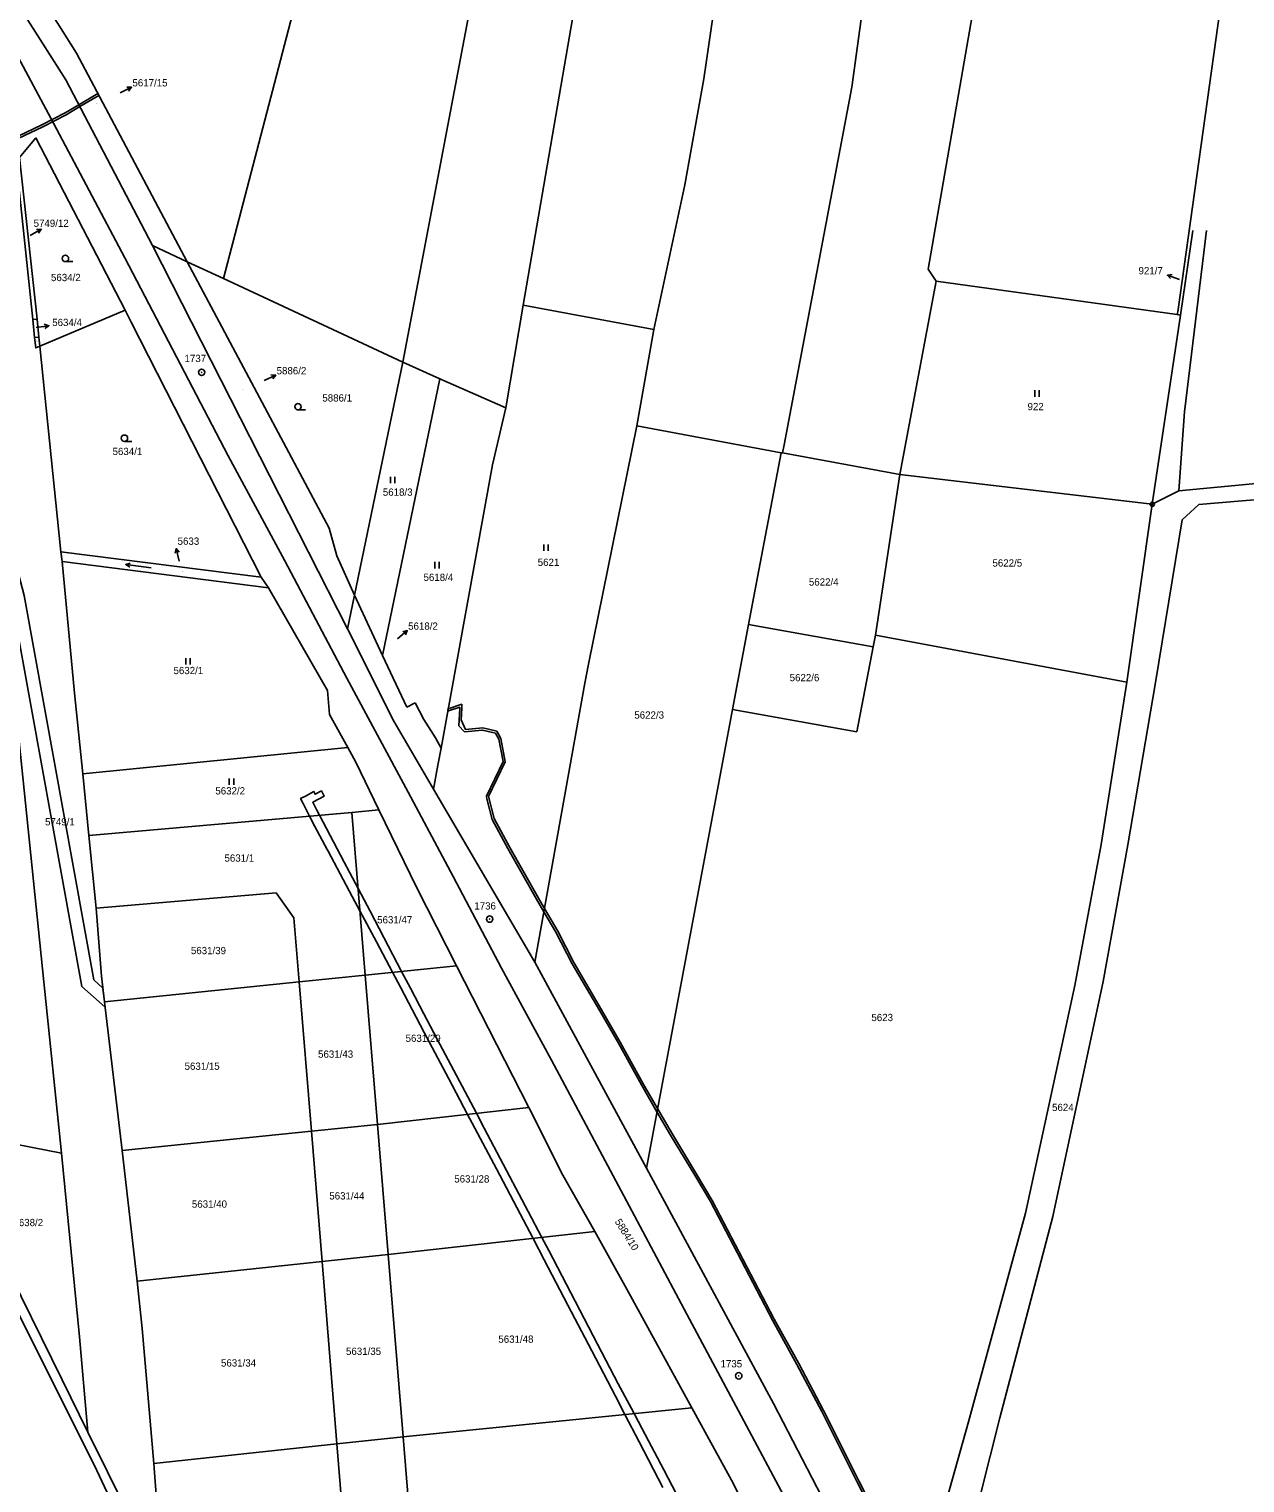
# Model space of a CAD drawing. Extents: x -735092 to -733385, y -1122435 to -1118992.
# Drawn here: x -734093.3 to -733808.8, y -1121933.9 to -1121593.8 of the extents above; entities that cross this region are included whole.
import ezdxf

# ---------------------------------------------------------------- set-up
doc = ezdxf.new("R2010")
doc.units = 0
for name, color, linetype in [('Vrstva 1', 7, 'Continuous'), ('Vrstva 10', 7, 'Continuous'), ('Vrstva 13', 7, 'Continuous'), ('Vrstva 16', 7, 'Continuous'), ('Vrstva 17', 7, 'Continuous'), ('Vrstva 18', 7, 'Continuous'), ('Vrstva 25', 7, 'Continuous'), ('Vrstva 27', 7, 'Continuous'), ('Vrstva 4', 7, 'Continuous')]:
    doc.layers.add(name, color=color, linetype=linetype)

msp = doc.modelspace()

# ---------------------------------------------------------------- linework, layer by layer
at = {"layer": 'Vrstva 1'}
for points in [[(-733875.65, -1121424.26), (-733900.77, -1121607.37)], [(-733977.66, -1121658.4), (-733946.34, -1121476.34)], [(-734005.87, -1121671.76), (-733978.34, -1121526.72)], [(-733811.12, -1121564.42), (-733824.52, -1121659.94)], [(-734101.71, -1121568.57), (-734082.23, -1121599.47)], [(-734100.75, -1121580.51), (-734084.7, -1121605.68)], [(-733882.88, -1121650), (-733870.98, -1121581.23)], [(-734029.87, -1121583.41), (-734047.83, -1121652.19)], [(-734082.23, -1121599.47), (-734056.29, -1121648.23)], [(-734084.7, -1121605.68), (-734064.45, -1121644.4)], [(-733900.77, -1121607.37), (-733916.64, -1121691.05)], [(-734095.52, -1121623.85), (-734091.73, -1121619.24)], [(-734091.73, -1121619.24), (-734070.84, -1121659.55)], [(-734092.41, -1121661.77), (-734096.3, -1121624.74), (-734095.52, -1121623.85)], [(-734095.52, -1121623.85), (-734091.45, -1121661.68)], [(-733823.82, -1121660.72), (-733821, -1121640.92)], [(-733817.78, -1121640.91), (-733822.95, -1121683.35)], [(-734064.45, -1121644.4), (-734018.79, -1121734.08)], [(-734064.45, -1121644.4), (-734056.29, -1121648.23)], [(-734056.29, -1121648.23), (-734023.08, -1121710.55)], [(-734056.29, -1121648.23), (-734047.83, -1121652.19)], [(-734047.83, -1121652.19), (-734005.87, -1121671.76)], [(-733889.57, -1121698.02), (-733881.01, -1121652.76)], [(-733881.01, -1121652.76), (-733882.88, -1121650)], [(-733824.6, -1121660.61), (-733881.01, -1121652.76)], [(-734070.84, -1121659.55), (-734090.77, -1121667.96)], [(-734070.84, -1121659.55), (-734069.41, -1121662.4)], [(-733981.73, -1121682.38), (-733977.66, -1121658.4)], [(-733977.66, -1121658.4), (-733947.14, -1121664.12)], [(-734091.45, -1121661.68), (-734092.41, -1121661.77)], [(-734092.41, -1121661.77), (-734092, -1121665.98)], [(-734091.45, -1121661.68), (-734090.99, -1121665.88)], [(-734069.41, -1121662.4), (-734039.01, -1121722.05)], [(-733830.45, -1121704.95), (-733823.82, -1121660.72)], [(-733824.52, -1121659.94), (-733824.6, -1121660.61)], [(-733823.82, -1121660.72), (-733824.6, -1121660.61)], [(-734092, -1121665.98), (-734090.99, -1121665.88)], [(-734090.77, -1121667.96), (-734091.75, -1121668.39), (-734092, -1121665.98)], [(-734090.99, -1121665.88), (-734090.77, -1121667.96)], [(-734090.77, -1121667.96), (-734085.86, -1121716.12)], [(-734005.87, -1121671.76), (-734017.16, -1121726.21)], [(-733997.17, -1121675.59), (-734005.87, -1121671.76)], [(-734010.59, -1121740.32), (-733997.17, -1121675.59)], [(-733981.73, -1121682.38), (-733997.17, -1121675.59)], [(-733984.85, -1121695.77), (-733981.73, -1121682.38)], [(-733822.95, -1121683.35), (-733824.25, -1121701.8)], [(-733962.43, -1121742.39), (-733951.07, -1121686.66)], [(-733924.95, -1121733.12), (-733917.31, -1121692.9)], [(-733917, -1121692.96), (-733916.64, -1121691.05)], [(-733984.85, -1121695.77), (-733996.9, -1121762.06)], [(-733895.27, -1121735.56), (-733889.57, -1121698.02)], [(-733819.53, -1121705.02), (-733772.5, -1121701.02)], [(-733836.45, -1121746.56), (-733830.45, -1121704.95)], [(-733823.46, -1121708.65), (-733819.53, -1121705.02)], [(-734023.08, -1121710.55), (-734021.29, -1121717.03)], [(-733829.73, -1121746.66), (-733823.46, -1121708.65)], [(-734085.86, -1121716.12), (-734085.6, -1121718.35)], [(-734085.86, -1121716.12), (-734039.01, -1121722.05)], [(-734021.29, -1121717.03), (-734017.16, -1121726.21)], [(-734085.6, -1121718.35), (-734082.66, -1121749.16)], [(-734085.6, -1121718.35), (-734037.31, -1121724.53)], [(-734039.01, -1121722.05), (-734037.31, -1121724.53)], [(-734037.31, -1121724.53), (-734023.46, -1121748.5)], [(-734017.16, -1121726.21), (-734018.79, -1121734.08)], [(-734017.16, -1121726.21), (-734015.7, -1121729.45)], [(-734010.59, -1121740.32), (-734015.7, -1121729.45)], [(-734018.79, -1121734.08), (-734007.98, -1121755.7)], [(-733928.73, -1121753.01), (-733924.95, -1121733.12)], [(-733895.8, -1121738.32), (-733924.95, -1121733.12)], [(-733895.8, -1121738.32), (-733895.27, -1121735.56)], [(-733895.27, -1121735.56), (-733836.45, -1121746.56)], [(-734004.87, -1121752.46), (-734010.59, -1121740.32)], [(-733899.62, -1121758.21), (-733895.8, -1121738.32)], [(-733963.23, -1121746.85), (-733962.43, -1121742.39)], [(-733974.96, -1121812.1), (-733963.23, -1121746.85)], [(-733842.4, -1121784.54), (-733836.45, -1121746.56)], [(-733836.2, -1121784.63), (-733829.73, -1121746.66)], [(-734096.58, -1121751.35), (-734089.85, -1121816.72)], [(-734082.66, -1121749.16), (-734080.75, -1121768.07)], [(-734023.46, -1121748.5), (-734023.04, -1121754.14)], [(-734004.87, -1121752.46), (-734002.96, -1121751.44)], [(-734002.96, -1121751.44), (-734000.89, -1121755.32)], [(-734023.04, -1121754.14), (-734018.75, -1121761.91)], [(-733948.86, -1121860.32), (-733928.73, -1121753.01)], [(-733928.73, -1121753.01), (-733899.62, -1121758.21)], [(-734007.98, -1121755.7), (-733998.64, -1121771.65)], [(-734000.89, -1121755.32), (-733998.2, -1121759.61)], [(-734080.75, -1121768.07), (-734018.75, -1121761.91)], [(-734018.75, -1121761.91), (-734016.88, -1121765.29)], [(-733998.2, -1121759.61), (-733996.9, -1121762.06)], [(-734016.88, -1121765.29), (-734011.43, -1121776.49)], [(-733996.9, -1121762.06), (-733997.62, -1121766.04)], [(-734080.75, -1121768.07), (-734079.3, -1121782.44)], [(-733998.64, -1121771.65), (-733997.62, -1121766.04)], [(-733998.64, -1121771.65), (-733974.96, -1121812.1)], [(-734079.3, -1121782.44), (-734017.78, -1121777.05)], [(-734017.78, -1121777.05), (-734011.43, -1121776.49)], [(-734017.78, -1121777.05), (-734014.66, -1121815.12)], [(-734011.43, -1121776.49), (-734002.59, -1121794.69)], [(-734079.3, -1121782.44), (-734077.64, -1121799.47)], [(-733848.6, -1121817.52), (-733842.4, -1121784.54)], [(-733841.98, -1121816.58), (-733836.2, -1121784.63)], [(-734077.64, -1121799.47), (-734035.52, -1121795.86)], [(-734035.52, -1121795.86), (-734031.32, -1121801.73)], [(-734002.59, -1121794.69), (-733993.29, -1121812.92)], [(-734077.64, -1121799.47), (-734076.35, -1121815.36)], [(-734031.32, -1121801.73), (-734030.1, -1121816.71)], [(-734014.66, -1121815.12), (-733993.29, -1121812.92)], [(-733993.29, -1121812.92), (-733976.37, -1121846.08)], [(-733974.96, -1121812.1), (-733948.86, -1121860.32)], [(-734076.35, -1121815.36), (-734075.64, -1121821.39)], [(-734030.1, -1121816.71), (-734014.66, -1121815.12)], [(-734014.66, -1121815.12), (-734011.79, -1121850.05)], [(-734089.85, -1121816.72), (-734085.71, -1121856.79)], [(-734075.64, -1121821.39), (-734030.1, -1121816.71)], [(-734030.1, -1121816.71), (-734027.25, -1121851.63)], [(-733860.13, -1121870.81), (-733848.6, -1121817.52)], [(-733853.74, -1121871.62), (-733841.98, -1121816.58)], [(-734075.64, -1121821.39), (-734071.56, -1121856.15)], [(-734011.79, -1121850.05), (-733976.37, -1121846.08)], [(-733976.37, -1121846.08), (-733968.39, -1121861.92)], [(-734027.25, -1121851.63), (-734011.79, -1121850.05)], [(-734011.79, -1121850.05), (-734009.29, -1121880.51)], [(-734114.51, -1121851.16), (-734085.71, -1121856.79)], [(-734114.51, -1121851.16), (-734085.55, -1121909.79)], [(-734071.56, -1121856.15), (-734027.25, -1121851.63)], [(-734027.25, -1121851.63), (-734024.75, -1121882.15)], [(-734085.71, -1121856.79), (-734081.52, -1121899.71)], [(-734071.56, -1121856.15), (-734067.98, -1121886.72)], [(-733948.86, -1121860.32), (-733919.08, -1121915.33)], [(-733968.39, -1121861.92), (-733960.89, -1121875.12)], [(-733873.47, -1121919.6), (-733860.13, -1121870.81)], [(-733866.1, -1121918.67), (-733853.74, -1121871.62)], [(-734009.29, -1121880.51), (-733960.89, -1121875.12)], [(-733960.89, -1121875.12), (-733953.4, -1121888.59)], [(-734024.75, -1121882.15), (-734009.29, -1121880.51)], [(-734009.29, -1121880.51), (-734005.79, -1121923.15)], [(-734067.98, -1121886.72), (-734024.75, -1121882.15)], [(-734024.75, -1121882.15), (-734021.27, -1121924.79)], [(-734067.98, -1121886.72), (-734066.81, -1121897.79)], [(-733953.4, -1121888.59), (-733938.22, -1121916.31)], [(-734066.81, -1121897.79), (-734064.13, -1121929.34)], [(-734081.52, -1121899.71), (-734079.52, -1121922.01)], [(-734085.55, -1121909.79), (-734079.52, -1121922.01)], [(-734005.79, -1121923.15), (-733938.22, -1121916.31)], [(-733938.22, -1121916.31), (-733928.94, -1121933.27)], [(-733919.08, -1121915.33), (-733885.18, -1121980.82)], [(-733881.78, -1121949.35), (-733873.47, -1121919.6)], [(-733875.09, -1121954.28), (-733866.1, -1121918.67)], [(-734079.52, -1121922.01), (-734061.09, -1121959.33)], [(-734064.13, -1121929.34), (-734021.27, -1121924.79)], [(-734021.27, -1121924.79), (-734005.79, -1121923.15)], [(-734021.27, -1121924.79), (-734018.17, -1121962.8)], [(-734005.79, -1121923.15), (-734002.17, -1121967.24)], [(-734064.13, -1121929.34), (-734062.57, -1121950.31)], [(-733928.94, -1121933.27), (-733915.89, -1121958.64)]]:
    msp.add_lwpolyline(points, dxfattribs=at)
at = {"layer": 'Vrstva 10'}
for points in [[(-734087.63, -1121615.83), (-734098.23, -1121596.04)], [(-734070.9, -1121647.29), (-734087.63, -1121615.83)], [(-734046.7, -1121693.62), (-734070.9, -1121647.29)], [(-734033.46, -1121718.24), (-734046.7, -1121693.62)], [(-734018.91, -1121745.65), (-734033.46, -1121718.24)], [(-734004.61, -1121772.34), (-734018.91, -1121745.65)], [(-733994.05, -1121792.05), (-734004.61, -1121772.34)], [(-733982.76, -1121813.53), (-733994.05, -1121792.05)], [(-733971.04, -1121835.03), (-733982.76, -1121813.53)], [(-733952.23, -1121870.23), (-733971.04, -1121835.03)], [(-733939.39, -1121894.46), (-733952.23, -1121870.23)], [(-733926.07, -1121919.37), (-733939.39, -1121894.46)], [(-733916.06, -1121938.12), (-733926.07, -1121919.37)]]:
    msp.add_lwpolyline(points, dxfattribs=at)
at = {"layer": 'Vrstva 13'}
for points in [[(-733935.41, -1121605.44), (-733932.13, -1121582.89)], [(-733939.85, -1121630.24), (-733935.41, -1121605.44)], [(-733947.14, -1121664.12), (-733939.85, -1121630.24)], [(-733951.07, -1121686.66), (-733947.14, -1121664.12)], [(-733951.07, -1121686.66), (-733917.31, -1121692.9)], [(-733917, -1121692.96), (-733917.31, -1121692.9)], [(-733889.57, -1121698.02), (-733917, -1121692.96)], [(-733824.25, -1121701.8), (-733728.81, -1121692.77)], [(-733889.57, -1121698.02), (-733830.45, -1121704.95)], [(-733830.45, -1121704.95), (-733824.25, -1121701.8)]]:
    msp.add_lwpolyline(points, dxfattribs=at)
at = {"layer": 'Vrstva 25'}
for points in [[(-734072.03, -1121608.7), (-734069.318, -1121607.418)], [(-734070.436, -1121607.394), (-734069.318, -1121607.418), (-734070.009, -1121608.298)], [(-734093.09, -1121642.07), (-734090.452, -1121640.644)], [(-734091.569, -1121640.679), (-734090.452, -1121640.644), (-734091.093, -1121641.559)], [(-734084.81, -1121648.21), (-734083.06, -1121648.21)], [(-733826.161, -1121652.191), (-733826.936, -1121651.384), (-733825.826, -1121651.249)], [(-733824.11, -1121652.39), (-733826.936, -1121651.384)], [(-734091.65, -1121663.65), (-734088.683, -1121663.212)], [(-734089.745, -1121662.864), (-734088.683, -1121663.212), (-734089.599, -1121663.852)], [(-734038.32, -1121675.99), (-734035.578, -1121674.775)], [(-734036.695, -1121674.723), (-734035.578, -1121674.775), (-734036.289, -1121675.637)], [(-733857.957, -1121679.815), (-733857.957, -1121678.315)], [(-733856.923, -1121679.815), (-733856.923, -1121678.315)], [(-734030.38, -1121682.9), (-734028.63, -1121682.9)], [(-734071, -1121690.27), (-734069.25, -1121690.27)], [(-734008.767, -1121700.035), (-734008.767, -1121698.535)], [(-734007.733, -1121700.035), (-734007.733, -1121698.535)], [(-734059.143, -1121716.438), (-734058.885, -1121715.35), (-734058.17, -1121716.209)], [(-734058.2, -1121718.27), (-734058.885, -1121715.35)], [(-733972.867, -1121715.855), (-733972.867, -1121714.355)], [(-733971.833, -1121715.855), (-733971.833, -1121714.355)], [(-734069.767, -1121719.708), (-734070.695, -1121719.084), (-734069.638, -1121718.717)], [(-734064.745, -1121719.856), (-734070.695, -1121719.084)], [(-733998.357, -1121719.965), (-733998.357, -1121718.465)], [(-733997.323, -1121719.965), (-733997.323, -1121718.465)], [(-734007.08, -1121736.46), (-734004.792, -1121734.52)], [(-734005.879, -1121734.786), (-734004.792, -1121734.52), (-734005.232, -1121735.548)], [(-734056.617, -1121742.475), (-734056.617, -1121740.975)], [(-734055.583, -1121742.475), (-734055.583, -1121740.975)], [(-734046.457, -1121770.625), (-734046.457, -1121769.125)], [(-734045.423, -1121770.625), (-734045.423, -1121769.125)]]:
    msp.add_lwpolyline(points, dxfattribs=at)
for centre, radius in [((-734084.81, -1121647.46), 0.75), ((-734052.93, -1121674.1), 0.75), ((-734052.93, -1121674.1), 0.032), ((-734030.38, -1121682.15), 0.75), ((-734071, -1121689.52), 0.75), ((-733830.45, -1121704.95), 0.5), ((-733830.45, -1121704.95), 0.032), ((-733985.53, -1121802.01), 0.75), ((-733985.53, -1121802.01), 0.032), ((-733927.24, -1121908.87), 0.75), ((-733927.24, -1121908.87), 0.032)]:
    msp.add_circle(centre, radius, dxfattribs=at)
at = {"layer": 'Vrstva 27'}
for points in [[(-734095.83, -1121619.37), (-734095.87, -1121618.84), (-734090.29, -1121616.22), (-734084.88, -1121613.39), (-734081.66, -1121611.5), (-734081.43, -1121611.94), (-734084.64, -1121613.83), (-734090.07, -1121616.66), (-734095.83, -1121619.37)], [(-734081.66, -1121611.5), (-734077.22, -1121608.89), (-734076.98, -1121609.33), (-734081.43, -1121611.94), (-734081.66, -1121611.5)], [(-734099.79, -1121711.74), (-734096.62, -1121717.99), (-734094.48, -1121726.34), (-734078.19, -1121816.24)], [(-734078.19, -1121816.24), (-734076.02, -1121818.16), (-734075.64, -1121821.39), (-734075.49, -1121822.63), (-734080.95, -1121817.8), (-734097.42, -1121726.98)], [(-733995.15, -1121753.29), (-733995.28, -1121753.17), (-733995.18, -1121752.6)], [(-733995.18, -1121752.6), (-733995.03, -1121752.73)], [(-733995.03, -1121752.73), (-733992.05, -1121751.77), (-733992, -1121752.7), (-733992.19, -1121755.42), (-733991.18, -1121757.66), (-733987.14, -1121757.28), (-733983.85, -1121758.06), (-733982.92, -1121759.76), (-733981.87, -1121765.2), (-733985.76, -1121773.36), (-733984.45, -1121778.49), (-733980.82, -1121785.29), (-733974.12, -1121797.12), (-733972.7, -1121799.53), (-733972.84, -1121800.29), (-733974.56, -1121797.37), (-733981.26, -1121785.53), (-733984.91, -1121778.68), (-733986.22, -1121773.9), (-733986.28, -1121773.28), (-733982.39, -1121765.14), (-733983.4, -1121759.94), (-733984.19, -1121758.5), (-733987.18, -1121757.78), (-733991.43, -1121758.19), (-733992.7, -1121756.8), (-733992.69, -1121755.47), (-733992.5, -1121752.7), (-733992.51, -1121752.45), (-733995.15, -1121753.29)], [(-733945.01, -1121934.95), (-733950.56, -1121924.29), (-733953.86, -1121917.89), (-733956.07, -1121913.64), (-733961.61, -1121902.99), (-733967.25, -1121892.36), (-733972.79, -1121881.69), (-733975.38, -1121876.73), (-733978.39, -1121870.99), (-733983.94, -1121860.46), (-733989.6, -1121849.79), (-733990.7, -1121847.69), (-733995.17, -1121839.19), (-734000.83, -1121828.55), (-734006.41, -1121817.95), (-734008.24, -1121814.46), (-734012.01, -1121807.3), (-734015.89, -1121800.07), (-734017.7, -1121796.69), (-734023.31, -1121786.14), (-734023.53, -1121785.74), (-734026.41, -1121780.36), (-734027.67, -1121777.92), (-734029.19, -1121775), (-734029.78, -1121773.84), (-734028.64, -1121773.24), (-734026.66, -1121772.2), (-734026.36, -1121772.79), (-734024.89, -1121772.04), (-734024.26, -1121773.29), (-734026.93, -1121774.67), (-734026.29, -1121775.88), (-734025.94, -1121776.57), (-734025.34, -1121777.71), (-734019.56, -1121788.69), (-734016.32, -1121794.85), (-734013.52, -1121800.18), (-734008.21, -1121810.36), (-734006.16, -1121814.25), (-734004.07, -1121818.2), (-734000.93, -1121824.15), (-733997.8, -1121830.09), (-733994.6, -1121836.12), (-733988.63, -1121847.45), (-733986.8, -1121850.91), (-733981.59, -1121860.86), (-733976.52, -1121870.43), (-733973.32, -1121876.5), (-733971.69, -1121879.58), (-733966.54, -1121889.45), (-733960.31, -1121901.47), (-733955.46, -1121910.71), (-733952.36, -1121916.47), (-733951.72, -1121917.68), (-733949.81, -1121921.29), (-733944.79, -1121930.89), (-733938.86, -1121942.21)], [(-733972.7, -1121799.53), (-733969.6, -1121804.8), (-733965.81, -1121812.19), (-733959.33, -1121823.25), (-733954.97, -1121830.77), (-733949.59, -1121840.54), (-733946.24, -1121846.34), (-733946.38, -1121847.09), (-733950.03, -1121840.78), (-733955.41, -1121831.01), (-733959.77, -1121823.51), (-733966.23, -1121812.45), (-733970.04, -1121805.04), (-733972.84, -1121800.29), (-733972.7, -1121799.53)], [(-733946.38, -1121847.09), (-733946.24, -1121846.34)], [(-733946.24, -1121846.34), (-733942.77, -1121852.33), (-733937.09, -1121861.68), (-733933.43, -1121867.84), (-733926.26, -1121881.57), (-733918.91, -1121895.61), (-733913.21, -1121905.94), (-733907.37, -1121917.01), (-733898.99, -1121933.7), (-733890.75, -1121949.72), (-733883.32, -1121963.64)], [(-733883.42, -1121964.52), (-733891.19, -1121949.96), (-733899.43, -1121933.92), (-733907.81, -1121917.23), (-733913.65, -1121906.18), (-733919.35, -1121895.85), (-733926.7, -1121881.81), (-733933.87, -1121868.08), (-733937.51, -1121861.94), (-733943.19, -1121852.59), (-733946.38, -1121847.09)]]:
    msp.add_lwpolyline(points, dxfattribs=at)
at = {"layer": 'Vrstva 4'}
for points in [[(-734077.42, -1121930.98), (-734127.19, -1121831.55)], [(-734073.85, -1121938.62), (-734077.42, -1121930.98)]]:
    msp.add_lwpolyline(points, dxfattribs=at)

# ---------------------------------------------------------------- texts
at = {"layer": 'Vrstva 16'}
for s, p in [('5617/15', (-734069.12, -1121607.22)), ('5749/12', (-734092.248, -1121640.08)), ('921/7', (-733833.676, -1121651.18)), ('5634/4', (-734087.888, -1121663.28)), ('5886/2', (-734035.38, -1121674.57)), ('5633', (-734058.55, -1121714.45)), ('5618/2', (-734004.6, -1121734.32))]:
    msp.add_text(s, height=1.7, dxfattribs=at).set_placement(p)
msp.add_text('5884/10', height=1.7, rotation=302.0024, dxfattribs=at).set_placement((-733956.314, -1121872.789))
at = {"layer": 'Vrstva 17'}
for s, p in [('1737', (-734056.93, -1121671.7)), ('1736', (-733989.12, -1121799.78)), ('1735', (-733931.49, -1121906.89))]:
    msp.add_text(s, height=1.7, dxfattribs=at).set_placement(p)
at = {"layer": 'Vrstva 18'}
for s, height, p in [('5617/15', 0.1, (-734077.77, -1121611.31)), ('5634/2', 1.7, (-734088.18, -1121652.77)), ('921/7', 0.1, (-733823.07, -1121652.49)), ('5634/4', 0.1, (-734091.684, -1121663.45)), ('5749/13', 0.1, (-734091.551, -1121666.83)), ('5886/2', 0.1, (-734043.6, -1121678.22)), ('5886/1', 1.7, (-734024.68, -1121680.94)), ('922', 1.7, (-733859.65, -1121682.96)), ('5634/1', 1.7, (-734073.77, -1121693.46)), ('5618/3', 1.7, (-734010.52, -1121702.98)), ('5621', 1.7, (-733974.28, -1121719.39)), ('5622/5', 1.7, (-733867.86, -1121719.55)), ('5618/4', 1.7, (-734001, -1121722.91)), ('5622/4', 1.7, (-733910.82, -1121724)), ('5618/2', 0.1, (-734012.24, -1121740.82)), ('5632/1', 1.7, (-734059.51, -1121744.71)), ('5622/6', 1.7, (-733915.32, -1121746.37)), ('5622/3', 1.7, (-733951.67, -1121755.12)), ('5632/2', 1.7, (-734049.72, -1121772.86)), ('5749/1', 1.7, (-734089.57, -1121780.1)), ('5631/1', 1.7, (-734047.58, -1121788.58)), ('5631/47', 1.7, (-734011.85, -1121803.02)), ('5631/39', 1.7, (-734055.44, -1121810.22)), ('5623', 1.7, (-733896.19, -1121825.88)), ('5631/29', 1.7, (-734005.2, -1121830.74)), ('5631/43', 1.7, (-734025.68, -1121834.45)), ('5631/15', 1.7, (-734056.92, -1121837.27)), ('5624', 1.7, (-733853.91, -1121846.91)), ('5631/28', 1.7, (-733993.81, -1121863.64)), ('5631/44', 1.7, (-734023.05, -1121867.61)), ('5631/40', 1.7, (-734055.21, -1121869.53)), ('5638/2', 1.7, (-734096.97, -1121873.85)), ('5631/48', 1.7, (-733983.49, -1121901.13)), ('5631/35', 1.7, (-734019.14, -1121903.97)), ('5631/34', 1.7, (-734048.4, -1121906.69))]:
    msp.add_text(s, height=height, dxfattribs=at).set_placement(p)
msp.add_text('5633', height=0.1, rotation=354.40282, dxfattribs=at).set_placement((-734057.352, -1121720.781))

doc.saveas('drawing.dxf')
